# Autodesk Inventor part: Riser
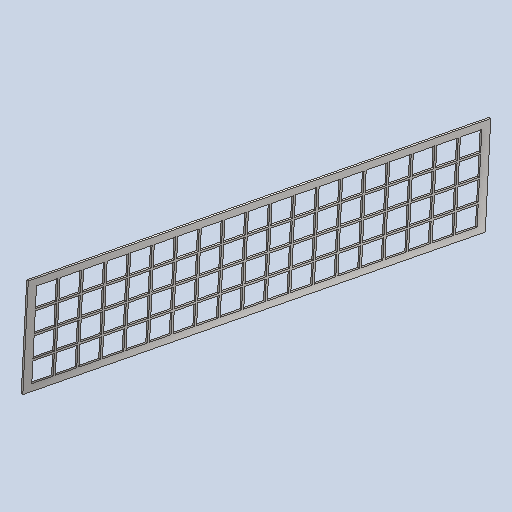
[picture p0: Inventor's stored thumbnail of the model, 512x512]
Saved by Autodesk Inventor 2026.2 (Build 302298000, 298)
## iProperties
RuleStatus: InUse
Created: 2022-06
Part Number: Riser
Material: Steel, Galvanized
Document SubType Name: Modeling
Designer: reaumed
Density: 7.85 g/cm^3
Appearance: Galvanized
Mass: 845.798 g
Surface Area: 1112.5 cm^2
Volume: 107.745 cm^3
AfterAnyParamChange0: pattern base location
AfterAnyUserParamChange0: pattern base location
Author: reaumed
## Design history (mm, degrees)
workplane "Work Plane1"
sketch "Sketch1"
  geometry: L1 (-342.9, -222.25)-(342.9, -222.25); L2 (342.9, -222.25)-(342.9, -381); L3 (342.9, -381)-(-342.9, -381); L4 (-342.9, -381)-(-342.9, -222.25); 3 further points
  constraints: 8 end point, 2 parallel, 1 coincident, 1 horizontal, 1 midpoint, 1 perpendicular
  dimensions: "ActualRiserWidth" = 685.8 distance of L2.end L3.end (= Width - 2 x StringerThickness); "ActualRiserHeight" = 158.75 distance of L1.end L2.end (= Rise - TreadThickness); "d5" = 222.25 distance from line of L1 point (0, 0) (= Rise + TreadThickness); "d6" = 0 horizontal distance of point (0, 0) point (0, -222.25)
extrude "Extrusion1" new body sketch "Sketch1" distance "d3" = 3.175 (= RiserThickness); taper "d4" = 0 deg
sketch "Sketch2"
  geometry: L1 (233.363, -330.2)-(265.113, -330.2); L2 (265.113, -330.2)-(265.113, -298.45); L3 (265.113, -298.45)-(233.363, -298.45); L4 (233.363, -298.45)-(233.363, -330.2); L5 (233.363, -330.2)-(265.113, -298.45); L6 (381, -342.9)-(381, 342.9) reference; L7 (381, 342.9)-(222.25, 342.9) reference; L8 (381, -342.9)-(222.25, 342.9); 3 further points
  constraints: 12 end point, 2 midpoint, 2 parallel, 1 horizontal, 1 perpendicular
  dimensions: "d7" = 31.75 distance of L2.end L3.end (= HoleSize); "HoleSize" = 31.75 distance of L3.end L1.start; "x_loc" = 314.325 vertical distance of point (249.237, -314.325) point (0, 0); "y_loc" = 52.3875 horizontal distance of point (301.625, 0) point (249.237, -314.325)
extrude "Grating Extrusion" cut sketch "Sketch2" extent not by distance; stored distance "d12" = 0; taper "d13" = 0 deg
body "Solid1"
pattern_linear "Grating Pattern" dims "d16" = 34.925 (= HoleSize + HoleSpacing), "d19" = 34.925 (= HoleSize + HoleSpacing)
other parameters: "Run" = 228.6 [user parameter; used in 1 equation term], "Width" = 762 [user parameter; used in 1 equation term], "Rise" = 190.5 [user parameter; used in 2 equation terms], "TreadThickness" = 31.75 [user parameter; used in 2 equation terms], "RiserThickness" = 3.175 [user parameter; used in 1 equation term], "d0" = 228.6 (= Run), "StringerThickness" = 38.1 [user parameter; used in 1 equation term], "HoleSpacing" = 3.175 [user parameter; used in 2 equation terms]
